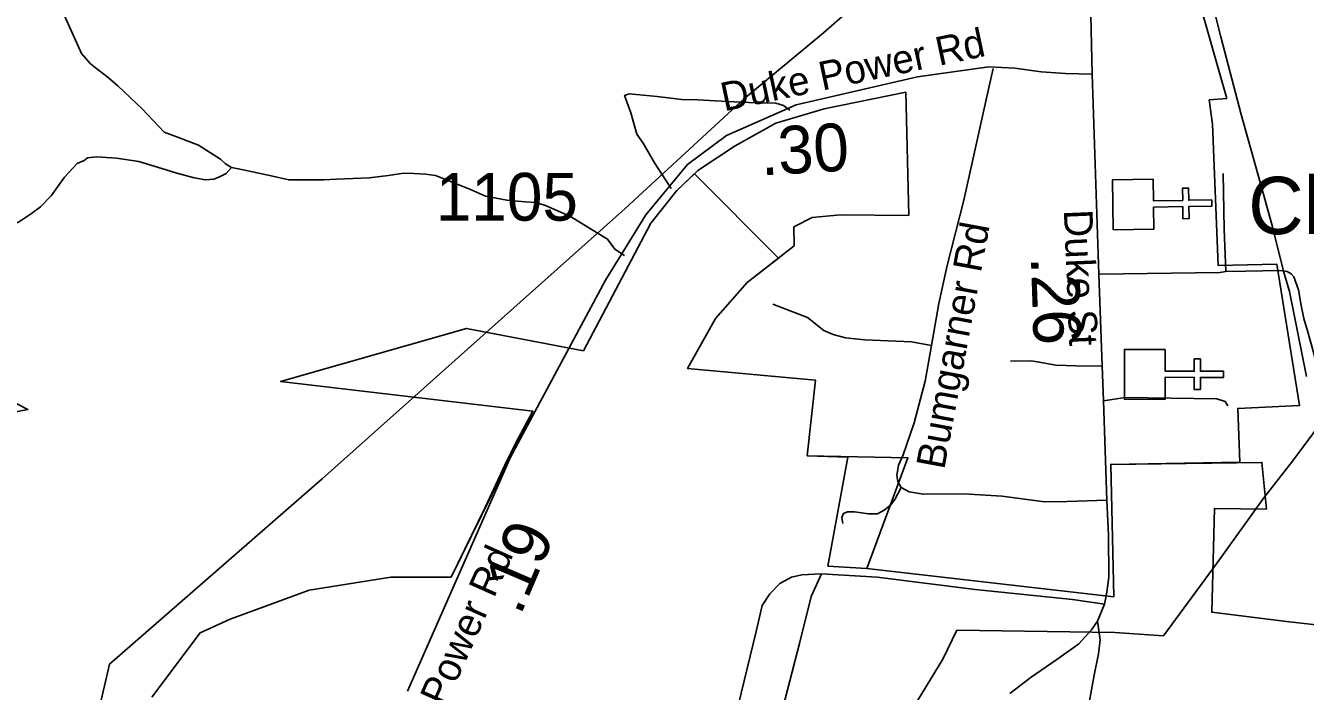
# Model space of a CAD drawing. Extents: x 1159738 to 1321356, y 736314 to 882035.
# Drawn here: x 1276893 to 1280239, y 747305 to 749048 of the extents above; entities that cross this region are included whole.
import ezdxf

# ---------------------------------------------------------------- set-up
doc = ezdxf.new("R2010")
doc.units = 0
for name, color, linetype in [('Exist Boundary Political City Limit New', 7, 'Continuous'), ('Exist Cultural Church CELL', 7, 'Continuous'), ('Exist Cultural Church Label', 7, 'Continuous'), ('Exist Hydrographic Lake Shore', 7, 'Continuous'), ('Exist Railroad Mainline', 7, 'Continuous'), ('Exist Road Non-System Type 51', 7, 'Continuous'), ('Exist Road Non-System Type 51 Label', 7, 'Continuous'), ('Exist Road Secondary Mileage Hundredths English Label', 7, 'Continuous'), ('Exist Road Secondary Type 51 Attributed', 7, 'Continuous'), ('Exist Road Secondary Type 51 Label', 7, 'Continuous'), ('Exist Road Secondary Type 51 Number Label', 7, 'Continuous'), ('Exist Utilities Electrical Transmission Line', 7, 'Continuous'), ('Map Preparation Boundary City Limit Buffer Line', 7, 'Continuous')]:
    doc.layers.add(name, color=color, linetype=linetype)

msp = doc.modelspace()

# ---------------------------------------------------------------- linework, layer by layer
at = {"layer": 'Exist Boundary Political City Limit New'}
for points in [[(1279877.1, 749408.7), (1280033.9, 748857.5), (1279987.8, 748853.6), (1279996.7, 748790.4), (1280010.9, 748420.2), (1280164.4, 748424.1), (1280223.9, 748053.7), (1280062.7, 748046.1), (1280068.2, 747905.4), (1279730.4, 747899.7), (1279738.1, 747553), (1279092.5, 747626.9), (1279200, 747916.9), (1278937.1, 747922.4), (1278958.2, 748120.2), (1278624.2, 748150.9), (1278697.2, 748281.5), (1278779.7, 748375.6), (1278902.5, 748471.7), (1278902.2, 748521.2), (1278949.8, 748546.2), (1279023.9, 748552.5), (1279202.2, 748551.3), (1279195.1, 748873.4), (1278981.1, 748830.6), (1278855.1, 748792.5), (1278748.1, 748733), (1278650.6, 748668.8), (1278595.9, 748616.5), (1278527.6, 748531.4), (1278351.6, 748197.1), (1278046.1, 748255.4), (1277559.9, 748116.2), (1278219.7, 748038.9), (1278005.6, 747604.2), (1277848.6, 747604.2), (1277634.7, 747570.9), (1277427.8, 747494.8), (1277349.3, 747459.1), (1277223.3, 747290.1)], [(1277223.3, 747290.1), (1277349.3, 747459.1), (1277427.8, 747494.8), (1277634.7, 747570.9), (1277848.6, 747604.2), (1278005.6, 747604.2), (1278094.8, 747786.6), (1278151.7, 747908.9), (1278181.9, 747969.2), (1278219.7, 748038.9), (1277559.9, 748116.2), (1278046.1, 748255.4), (1278351.6, 748197.1), (1278527.6, 748531.4), (1278595.9, 748616.5), (1278642.2, 748660.4), (1278862.2, 748439.8), (1278779.7, 748375.6), (1278697.2, 748281.5), (1278624.2, 748150.9), (1278958.2, 748120.2), (1278937.1, 747922.4), (1279043.3, 747919), (1278991.1, 747633.5), (1279092.5, 747626.9)], [(1279092.5, 747626.9), (1279738.1, 747553), (1279730.4, 747899.7)], [(1279730.4, 747899.7), (1280125.7, 747905), (1280137.6, 747782.8), (1280001.3, 747784.6), (1279994.4, 747512.9), (1280189.9, 747488.6), (1280390.8, 747465.6), (1280453.6, 747384.9), (1280694.2, 747157.2), (1280762.5, 747052.3), (1280902.3, 746866.1), (1281002.8, 746741), (1281164, 746531), (1281300.3, 746355.5), (1281615.1, 745919.3), (1281670.1, 745764.8), (1281704.5, 745572.4), (1281700.6, 745424.3), (1281700.6, 745194.9), (1281696.9, 745054), (1281693, 744910), (1281709.9, 744721.1)]]:
    msp.add_lwpolyline(points, dxfattribs=at)
at = {"layer": 'Exist Cultural Church CELL'}
for points in [[(1279841.3, 748646.1), (1279842.4, 748589.2), (1279918.5, 748590.5), (1279918, 748622.5), (1279933.9, 748622.8), (1279934.5, 748590.8), (1279994.6, 748591.8), (1279994.9, 748575.8), (1279934.7, 748574.7), (1279935.3, 748542.8), (1279919.3, 748542.5), (1279918.8, 748574.5), (1279842.6, 748573.2), (1279843.5, 748515.5), (1279737.1, 748513.7), (1279734.9, 748644.3)], [(1279872.7, 748200.6), (1279872.8, 748143.6), (1279948.9, 748143.5), (1279948.9, 748175.5), (1279964.9, 748175.5), (1279964.9, 748143.5), (1280025, 748143.4), (1280025, 748127.4), (1279964.8, 748127.5), (1279964.8, 748095.5), (1279948.8, 748095.5), (1279948.9, 748127.5), (1279872.7, 748127.6), (1279872.5, 748069.9), (1279766.1, 748070.1), (1279766.3, 748200.7)]]:
    msp.add_lwpolyline(points, close=True, dxfattribs=at)
at = {"layer": 'Exist Hydrographic Lake Shore'}
msp.add_lwpolyline([(1276820.6, 748028.6), (1276899.2, 748042.9), (1276825.5, 748081)], dxfattribs=at)
at = {"layer": 'Exist Railroad Mainline'}
msp.add_lwpolyline([(1280242.5, 748130), (1280225, 748216.5), (1280198, 748352.2), (1280182.5, 748405.1), (1280152.5, 748524.8), (1280116.3, 748656.4), (1280071.8, 748815.7), (1280018, 749018.3), (1280004.6, 749073.3)], dxfattribs=at)
at = {"layer": 'Exist Road Non-System Type 51'}
for points in [[(1277431.8, 748676.5), (1277416.2, 748685.9), (1277402.6, 748698.4), (1277383.9, 748710.9), (1277345.3, 748734.9), (1277293.2, 748754.8), (1277255.7, 748769.4), (1277198.4, 748829.8), (1277134, 748890.8), (1277104.9, 748915.9), (1277079.8, 748934.6), (1277062.1, 748949.2), (1277039.2, 748975.3), (1276992.3, 749079.6)], [(1279422.8, 748936.2), (1279410.5, 748881.5), (1279346.4, 748591.5), (1279302.4, 748420.5), (1279281, 748320.7), (1279261.4, 748211)], [(1278891, 748826.4), (1278874.8, 748838.5), (1278854.5, 748845.3), (1278784.4, 748846.6), (1278726.4, 748849.3), (1278650.9, 748853.4), (1278609, 748854.7), (1278544.3, 748862.8), (1278471.4, 748869.6), (1278459.3, 748865.5), (1278475.5, 748819.6), (1278491.7, 748764.3), (1278507.9, 748740), (1278537.5, 748688.7), (1278581.4, 748621.5)], [(1277431.8, 748676.5), (1277417.5, 748660.7), (1277398.8, 748651.3), (1277385.2, 748646.1), (1277363.3, 748644), (1277334.1, 748649.2), (1277288.3, 748661.8), (1277249.7, 748674.3), (1277189.3, 748692), (1277130.9, 748701.4), (1277078.8, 748704.5), (1277054.8, 748702.4), (1277046.5, 748695.1), (1277027.7, 748686.8), (1276995.4, 748651.3), (1276960, 748602.3), (1276931.9, 748574.1), (1276908.9, 748556.4), (1276874.5, 748533.5), (1276833.9, 748518.9), (1276769.3, 748499.1), (1276691.1, 748454.2), (1276585.3, 748411.8)], [(1278459.5, 748446.5), (1278433.8, 748462.9), (1278415, 748488.9), (1278370.2, 748516.1), (1278318.1, 748548.4), (1278252.4, 748577.6), (1278227.4, 748584.9), (1278200.3, 748587), (1278169.1, 748589.1), (1278151.3, 748591.2), (1278096.1, 748601.6), (1278056.5, 748619.3), (1277964.8, 748655.8), (1277938.7, 748658.9), (1277908.5, 748661), (1277881.4, 748662.1), (1277841.8, 748655.8), (1277791.8, 748649.6), (1277706.3, 748646.4), (1277671.9, 748644.3), (1277618.8, 748644.3), (1277581.3, 748644.3), (1277535.4, 748654.8), (1277462, 748670.3), (1277431.8, 748676.5)], [(1280031.5, 748404.5), (1280026.8, 748515.4), (1280024.6, 748661.3)], [(1279699.7, 748397.4), (1280015.3, 748402.2), (1280031.5, 748404.5)], [(1280031.5, 748404.5), (1280083.1, 748405.6), (1280127, 748406.4), (1280156.3, 748406.9), (1280181.1, 748406), (1280191.3, 748404.8), (1280202.3, 748398.3), (1280209.2, 748390.6), (1280221, 748356.8), (1280228.3, 748315.3), (1280235.2, 748281.5), (1280245.3, 748249.5), (1280259.1, 748199.3), (1280285, 748093.1), (1280302.3, 748037.8), (1280313.8, 747972.8), (1280323.2, 747901.3), (1280332.6, 747820.8)], [(1278847, 748318.8), (1278937.4, 748283.7), (1278980.5, 748250), (1279004.8, 748239.2), (1279037.2, 748231.1), (1279087.1, 748225.7), (1279209.9, 748220.3), (1279261.4, 748211)], [(1279261.4, 748211), (1279245, 748117.6), (1279216.9, 748008.6), (1279187.6, 747924.4), (1279175.5, 747897.7), (1279171.5, 747870.9), (1279174.2, 747854.9), (1279182.2, 747838.9), (1279203.6, 747828.2), (1279239.6, 747821.5), (1279345.1, 747822.8), (1279446.6, 747816.2), (1279557.5, 747801.5), (1279616.2, 747802.8), (1279720.5, 747806.4)], [(1279468.5, 748169.4), (1279522.5, 748170.3), (1279543.7, 748167.4), (1279587.2, 748159.3), (1279666.8, 748156.6), (1279707.9, 748158)], [(1279711.7, 748066.4), (1279768.1, 748075), (1280008.2, 748070.9), (1280029.8, 748064.5), (1280036.3, 748053)], [(1279182.2, 747838.9), (1279166.2, 747807.5), (1279154.2, 747792.8), (1279138.2, 747779.5), (1279120.8, 747770.1), (1279096.8, 747770.1), (1279060.7, 747775.5), (1279042, 747775.5), (1279031.3, 747771.5), (1279027.3, 747760.8), (1279030, 747744.7)], [(1278714.4, 747104.9), (1278756.5, 747268.3), (1278803.1, 747462), (1278819.2, 747530.3), (1278839.3, 747561), (1278865, 747588), (1278896, 747604.2), (1278923, 747610.9), (1278974.2, 747613.6)], [(1278974.2, 747613.6), (1278947.2, 747554.2), (1278916.7, 747430.9), (1278854.2, 747188.8), (1278830.1, 747113)], [(1278974.2, 747613.6), (1279119.7, 747604.6), (1279376.4, 747572.1), (1279630.2, 747545.7), (1279714.4, 747533.9)], [(1279695.4, 747489.7), (1279702.7, 747440.7), (1279698.6, 747404.2), (1279687.1, 747348.4), (1279641.2, 747093.3)]]:
    msp.add_lwpolyline(points, dxfattribs=at)
at = {"layer": 'Exist Road Secondary Type 51 Attributed'}
for points in [[(1279677.8, 749115), (1279682.2, 748921.1)], [(1279682.2, 748921.1), (1279611.8, 748922.9), (1279548.3, 748927.3), (1279479.8, 748936.7), (1279411.9, 748939.8), (1279225.3, 748913.9), (1278908.4, 748841), (1278726.2, 748760.8), (1278624.2, 748684.3), (1278514.9, 748553), (1278409.3, 748381.7), (1278161.5, 747918.8), (1277891.7, 747306.2)], [(1279682.2, 748921.1), (1279699.7, 748397.4), (1279707.9, 748158), (1279711.7, 748066.4), (1279720.5, 747806.4)], [(1279720.5, 747806.4), (1279724.2, 747714.7), (1279725.5, 747604.7), (1279720.5, 747565), (1279715.9, 747542.3)], [(1279715.9, 747542.3), (1279714.4, 747533.9), (1279695.4, 747489.7), (1279680.3, 747467), (1279647.1, 747430.1), (1279589.9, 747389.2), (1279522, 747342.6), (1279466.5, 747300.4)]]:
    msp.add_lwpolyline(points, dxfattribs=at)
at = {"layer": 'Exist Utilities Electrical Transmission Line'}
for points in [[(1279166.1, 749193), (1278979.6, 749029.1), (1278774.3, 748859), (1278460.9, 748569.7), (1277668.4, 747861.6), (1277112.8, 747377), (1276989, 746840.8), (1276963, 746691), (1277163.1, 746622.1), (1277389.3, 746543.9), (1277427.5, 746575.7)], [(1277488.9, 746268), (1277510.8, 746044.2), (1277524.3, 745922.4), (1277778.7, 745881.5), (1278034, 745877.4), (1278218, 745855.6), (1278510.6, 746138.3), (1278793.1, 746595.3), (1278914, 746784.1), (1279138.5, 747139.5), (1279291.4, 747390.2), (1279328.1, 747465.8), (1279741.3, 747459.9), (1279868, 747451.2), (1280008.9, 747642.4), (1280131, 747812), (1280205.4, 747908.3), (1280287.1, 748016.8), (1280460.6, 748220), (1280620.2, 748437.3), (1280760, 748610.9), (1280881.1, 748758.7), (1281060.7, 748950.1), (1281223.6, 749142.3)]]:
    msp.add_lwpolyline(points, dxfattribs=at)
at = {"layer": 'Map Preparation Boundary City Limit Buffer Line'}
for points in [[(1279877.1, 749408.7), (1280033.9, 748857.5), (1279987.8, 748853.6), (1279996.7, 748790.4), (1280010.9, 748420.2), (1280164.4, 748424.1), (1280223.9, 748053.7), (1280062.7, 748046.1), (1280068.2, 747905.4), (1279730.4, 747899.7), (1279738.1, 747553), (1279092.5, 747626.9), (1279200, 747916.9), (1278937.1, 747922.4), (1278958.2, 748120.2), (1278624.2, 748150.9), (1278697.2, 748281.5), (1278779.7, 748375.6), (1278902.5, 748471.7), (1278902.2, 748521.2), (1278949.8, 748546.2), (1279023.9, 748552.5), (1279202.2, 748551.3), (1279195.1, 748873.4), (1278981.1, 748830.6), (1278855.1, 748792.5), (1278748.1, 748733), (1278650.6, 748668.8), (1278595.9, 748616.5), (1278527.6, 748531.4), (1278351.6, 748197.1), (1278046.1, 748255.4), (1277559.9, 748116.2), (1278219.7, 748038.9), (1278005.6, 747604.2), (1277848.6, 747604.2), (1277634.7, 747570.9), (1277427.8, 747494.8), (1277349.3, 747459.1), (1277223.3, 747290.1)], [(1277223.3, 747290.1), (1277349.3, 747459.1), (1277427.8, 747494.8), (1277634.7, 747570.9), (1277848.6, 747604.2), (1278005.6, 747604.2), (1278094.8, 747786.6), (1278151.7, 747908.9), (1278181.9, 747969.2), (1278219.7, 748038.9), (1277559.9, 748116.2), (1278046.1, 748255.4), (1278351.6, 748197.1), (1278527.6, 748531.4), (1278595.9, 748616.5), (1278642.2, 748660.4), (1278862.2, 748439.8), (1278779.7, 748375.6), (1278697.2, 748281.5), (1278624.2, 748150.9), (1278958.2, 748120.2), (1278937.1, 747922.4), (1279043.3, 747919), (1278991.1, 747633.5), (1279092.5, 747626.9)], [(1279092.5, 747626.9), (1279738.1, 747553), (1279730.4, 747899.7)], [(1279730.4, 747899.7), (1280125.7, 747905), (1280137.6, 747782.8), (1280001.3, 747784.6), (1279994.4, 747512.9), (1280189.9, 747488.6), (1280390.8, 747465.6), (1280453.6, 747384.9), (1280694.2, 747157.2), (1280762.5, 747052.3), (1280902.3, 746866.1), (1281002.8, 746741), (1281164, 746531), (1281300.3, 746355.5), (1281615.1, 745919.3), (1281670.1, 745764.8), (1281704.5, 745572.4), (1281700.6, 745424.3), (1281700.6, 745194.9), (1281696.9, 745054), (1281693, 744910), (1281709.9, 744721.1)]]:
    msp.add_lwpolyline(points, dxfattribs=at)

# ---------------------------------------------------------------- texts
at = {"layer": 'Exist Cultural Church Label'}
msp.add_text('Church of God', height=150, dxfattribs=at).set_placement((1280089.9, 748502.3))
at = {"layer": 'Exist Road Non-System Type 51 Label'}
msp.add_text('Duke Power Rd', height=75, rotation=65.9371, dxfattribs=at).set_placement((1277883.5, 747023.4))
at = {"layer": 'Exist Road Secondary Mileage Hundredths English Label'}
for s, rotation, p in [('.30', 3.3198, (1278817.1, 748655.8)), ('.26', 271.9621, (1279521.5, 748442.6)), ('.19', 66.8757, (1278186.8, 747501.6))]:
    msp.add_text(s, height=125, rotation=rotation, dxfattribs=at).set_placement(p)
at = {"layer": 'Exist Road Secondary Type 51 Label'}
for s, rotation, p in [('Duke Power Rd', 11.9939, (1278719.7, 748823.3)), ('Bumgarner Rd', 79.476, (1279295, 747884.1)), ('Duke St', 272.4005, (1279607.6, 748565.3))]:
    msp.add_text(s, height=75, rotation=rotation, dxfattribs=at).set_placement(p)
at = {"layer": 'Exist Road Secondary Type 51 Number Label'}
msp.add_text('1105', height=125, dxfattribs=at).set_placement((1277965.6, 748537.5))

doc.saveas('drawing.dxf')
